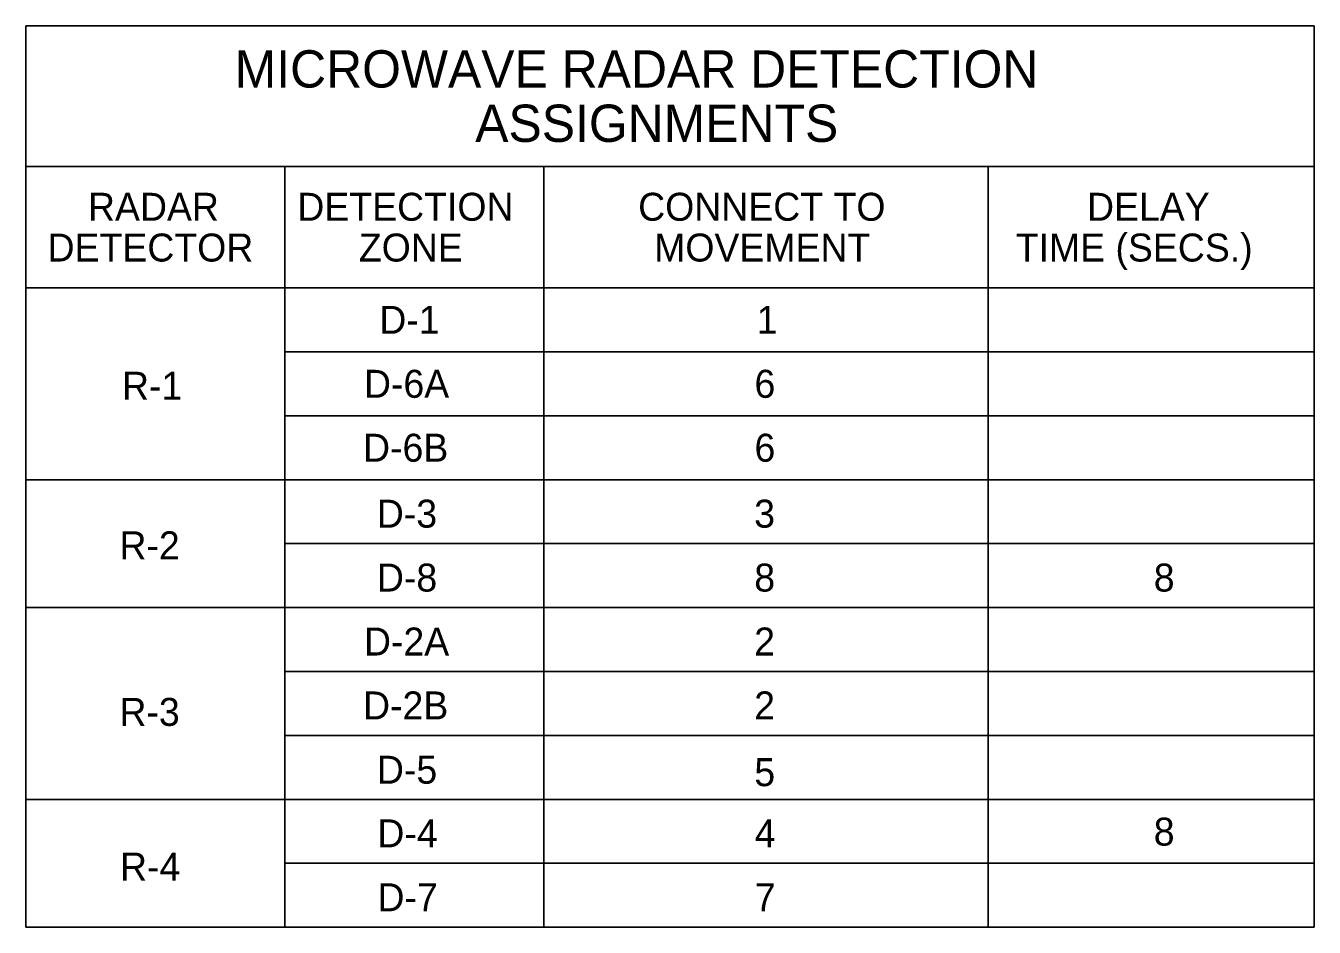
# Model space of a CAD drawing. Extents: x 0 to 1428, y -128 to 567.
# Drawn here: x 0.4586 to 0.7103, y 0.4109 to 0.5871 of the extents above; entities that cross this region are included whole.
import ezdxf

# ---------------------------------------------------------------- set-up
doc = ezdxf.new("R2010")
doc.units = 0
doc.layers.add('SumBoxLines_dp', color=7, linetype='Continuous')
doc.layers.add('TextLabel', color=7, linetype='Continuous')

msp = doc.modelspace()

# ---------------------------------------------------------------- linework, layer by layer
at = {"layer": 'SumBoxLines_dp'}
for p, q in [((0.45857, 0.58707), (0.71034, 0.58707)), ((0.45857, 0.58707), (0.45857, 0.41089)), ((0.71034, 0.58707), (0.71034, 0.41089)), ((0.45857, 0.55958), (0.71034, 0.55958)), ((0.45857, 0.55958), (0.71034, 0.55958)), ((0.50917, 0.55958), (0.50917, 0.41089)), ((0.55977, 0.55958), (0.55977, 0.41089)), ((0.64662, 0.55958), (0.64662, 0.41089)), ((0.45857, 0.53584), (0.71034, 0.53584)), ((0.45857, 0.53584), (0.71034, 0.53584)), ((0.50917, 0.52334), (0.71034, 0.52334)), ((0.50917, 0.52334), (0.71034, 0.52334)), ((0.50917, 0.51085), (0.71034, 0.51085)), ((0.50917, 0.51085), (0.71034, 0.51085)), ((0.45857, 0.49835), (0.71034, 0.49835)), ((0.50917, 0.49835), (0.71034, 0.49835)), ((0.50917, 0.48586), (0.71034, 0.48586)), ((0.45857, 0.47336), (0.71034, 0.47336)), ((0.50917, 0.47336), (0.71034, 0.47336)), ((0.50917, 0.46087), (0.71034, 0.46087)), ((0.50917, 0.46087), (0.71034, 0.46087)), ((0.50917, 0.44837), (0.71034, 0.44837)), ((0.50917, 0.44837), (0.71034, 0.44837)), ((0.45857, 0.43588), (0.71034, 0.43588)), ((0.50917, 0.43588), (0.71034, 0.43588)), ((0.50917, 0.42338), (0.71034, 0.42338)), ((0.50917, 0.42338), (0.71034, 0.42338)), ((0.45857, 0.41089), (0.71034, 0.41089))]:
    msp.add_line(p, q, dxfattribs=at)

# ---------------------------------------------------------------- texts
at = {"layer": 'TextLabel'}
for s, height, p in [('MICROWAVE RADAR DETECTION', 0.0072888, (0.49939, 0.57499)), ('ASSIGNMENTS', 0.0072888, (0.54639, 0.56437)), ('RADAR', 0.005467, (0.47072, 0.54896)), ('DETECTION', 0.005467, (0.51163, 0.54896)), ('CONNECT TO', 0.005467, (0.57823, 0.54896)), ('DELAY', 0.005467, (0.66594, 0.54896)), ('DETECTOR', 0.005467, (0.46282, 0.54099)), ('ZONE', 0.005467, (0.52365, 0.54099)), ('MOVEMENT', 0.005467, (0.58136, 0.54099)), ('TIME (SECS.)', 0.0054666, (0.65201, 0.54099)), ('D-1', 0.005467, (0.52765, 0.52686)), ('1', 0.00547, (0.6014, 0.52686)), ('R-1', 0.005467, (0.47737, 0.51398)), ('D-6A', 0.005467, (0.52465, 0.51436)), ('6', 0.00547, (0.60096, 0.51436)), ('D-6B', 0.005467, (0.52447, 0.50187)), ('6', 0.00547, (0.60096, 0.50187)), ('D-3', 0.005467, (0.52716, 0.48898)), ('3', 0.00547, (0.6009, 0.48898)), ('R-2', 0.005467, (0.47687, 0.48279)), ('D-8', 0.005467, (0.52718, 0.47649)), ('8', 0.00547, (0.60092, 0.47649)), ('8', 0.00547, (0.67898, 0.47649)), ('D-2A', 0.005467, (0.52465, 0.46399)), ('2', 0.00547, (0.6009, 0.46399)), ('R-3', 0.005467, (0.47687, 0.45024)), ('D-2B', 0.005467, (0.52447, 0.4515)), ('2', 0.00547, (0.6009, 0.4515)), ('D-5', 0.005467, (0.52718, 0.43894)), ('5', 0.00547, (0.60093, 0.43846)), ('D-4', 0.005467, (0.52727, 0.42651)), ('4', 0.00547, (0.60101, 0.42651)), ('8', 0.00547, (0.67898, 0.42684)), ('R-4', 0.005467, (0.47698, 0.42001)), ('D-7', 0.005467, (0.52729, 0.41401)), ('7', 0.00547, (0.60103, 0.41401))]:
    msp.add_text(s, height=height, dxfattribs=at).set_placement(p)

doc.saveas('drawing.dxf')
